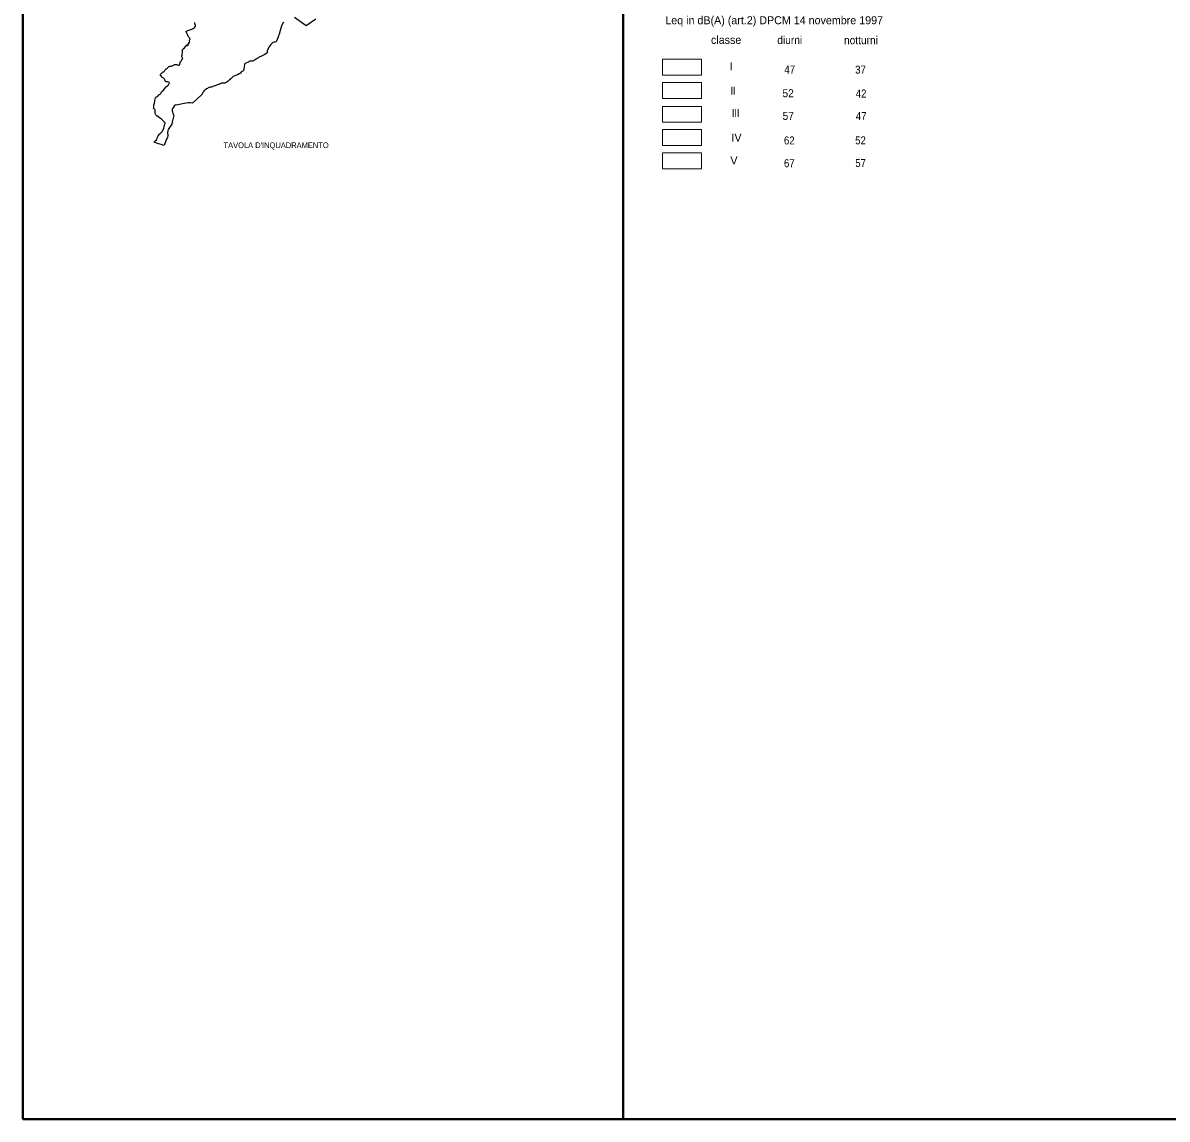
# Model space of a CAD drawing. Extents: x 654952 to 658955, y 890426 to 894481.
# Drawn here: x 654952 to 656954, y 890426 to 892344 of the extents above; entities that cross this region are included whole.
import ezdxf
from ezdxf.enums import TextEntityAlignment as Align

# ---------------------------------------------------------------- set-up
doc = ezdxf.new("R2010")
doc.units = 0
doc.header["$LTSCALE"] = 4
doc.layers.add('60', color=7, linetype='Continuous', lineweight=35)

msp = doc.modelspace()

# ---------------------------------------------------------------- linework, layer by layer
at = {"layer": '60', "lineweight": 40}
for p, q in [((654952.15, 892994.48), (654952.15, 890425.88)), ((656002.15, 892994.48), (656002.15, 890425.88)), ((657055.17, 890425.88), (654952.15, 890425.88))]:
    msp.add_line(p, q, dxfattribs=at)
at = {"layer": '60', "lineweight": 25}
for points in [[(655243.29, 892308.87), (655242.85, 892309.11), (655242.53, 892309.19), (655242.27, 892309.55), (655242.27, 892309.72), (655242.53, 892310.16), (655242.99, 892310.28), (655243.61, 892310.35), (655244.07, 892310.96), (655243.75, 892312.08), (655243.87, 892314.07), (655244.51, 892315), (655244.45, 892316.23), (655243.95, 892317.28), (655242.85, 892318.4), (655241.77, 892319.52), (655241.19, 892320.39), (655240.43, 892321.95), (655240.05, 892323.28), (655239.53, 892324.67), (655239.21, 892325.72), (655238.71, 892326.35), (655237.67, 892327.32), (655237.41, 892328.07), (655237.49, 892329), (655238.19, 892329.48), (655239.33, 892329.92), (655240.69, 892330.36), (655242.33, 892330.83), (655244.31, 892331.39), (655247.63, 892332.63), (655250.25, 892333.99), (655252.05, 892334.99), (655253.19, 892336.08), (655254.21, 892337.83), (655254.21, 892338.32), (655253.91, 892340.19), (655253.13, 892341.6), (655252.81, 892342.72), (655252.75, 892343.52)], [(655252.75, 892343.52), (655252.75, 892344.52)], [(655408.31, 892345), (655405.95, 892341.12), (655405.19, 892339.47), (655403.55, 892334.71), (655401.11, 892326.08), (655400.23, 892323.31), (655399.53, 892321.2), (655398.25, 892317.72), (655396.97, 892314.51), (655395.63, 892311.96), (655394.49, 892310.48), (655393.41, 892309.96), (655391.83, 892309.72), (655389.59, 892309.15), (655388.43, 892308.36), (655385.81, 892305.68), (655382.55, 892300.96), (655379.87, 892295.88)], [(655464.83, 892350.4), (655447.49, 892338.48), (655427.31, 892353.16)], [(655227.11, 892273.48), (655227.37, 892274.67), (655227.93, 892275.91), (655228.95, 892276.84), (655229.73, 892278), (655230.17, 892279.24), (655231.13, 892280.56), (655231.61, 892280.95), (655231.75, 892281.63), (655231.35, 892282.32), (655230.85, 892283.31), (655230.33, 892284.12), (655230.39, 892285.4), (655230.85, 892287.03), (655231.05, 892289.19), (655231.29, 892291.55), (655231.29, 892293.52), (655231.17, 892294.95), (655231.05, 892295.88), (655231.17, 892296.75), (655231.69, 892297.31), (655232.71, 892298.28), (655234.61, 892300.23), (655236.59, 892302.27), (655237.69, 892303.75), (655238.07, 892305.12), (655238.19, 892305.52), (655238.71, 892305.32), (655239.21, 892304.52), (655239.65, 892303.96), (655240.87, 892304.04), (655241.37, 892304.71), (655241.45, 892305.64), (655241.37, 892306.63), (655241.45, 892307.39), (655241.71, 892307.44), (655242.33, 892307.68), (655242.93, 892307.92), (655243.29, 892308.31), (655243.29, 892308.87)], [(655379.87, 892295.88), (655379.55, 892294.11), (655379.61, 892292.63), (655379.19, 892291.6), (655377.71, 892290.19), (655375.41, 892288.59), (655372.09, 892286.91), (655368.45, 892285.19), (655366.23, 892284.15), (655364.37, 892282.47), (655362.09, 892281.4), (655360.41, 892280.48), (655357.41, 892278.32), (655355.37, 892277.52), (655353.53, 892276.91), (655350.85, 892276.52), (655348.93, 892276.52), (655347.65, 892276.15), (655346.55, 892275.04), (655344.91, 892274.48), (655342.17, 892273.48), (655340.95, 892272.8), (655339.93, 892271.27), (655339.59, 892270.08), (655339.23, 892267.88), (655338.41, 892262), (655337.97, 892260.39), (655337.13, 892259.28), (655335.73, 892258.47), (655334.13, 892257.28), (655332.53, 892255.99), (655330.23, 892254.68), (655327.55, 892253.03), (655323.85, 892251.4), (655320.27, 892249.8), (655319.01, 892248.55), (655317.33, 892247.12), (655315.67, 892245.76), (655313.69, 892243.96), (655311.15, 892241.87)], [(655192.71, 892253.15), (655193.33, 892254.12), (655193.91, 892255), (655194.99, 892255.6), (655195.89, 892256.16), (655196.61, 892257.36), (655197.03, 892257.76), (655197.73, 892257.95), (655198.69, 892258.32), (655199.77, 892259.43), (655200.41, 892260.4), (655201.17, 892261.4), (655201.69, 892262.28), (655202.07, 892263.15), (655202.59, 892263.32), (655203.35, 892263.32), (655203.99, 892263.76), (655205.07, 892264.63), (655205.71, 892265.39), (655206.29, 892266), (655206.73, 892266.75), (655207.43, 892267.24), (655208.19, 892267.48), (655209.21, 892267.72), (655210.43, 892267.96), (655211.91, 892268.23), (655213.43, 892268.52), (655214.59, 892269.04), (655215.81, 892269.88), (655216.77, 892270.32), (655217.65, 892270.64), (655219.05, 892270.76), (655220.27, 892270.76), (655221.35, 892270.64), (655222.65, 892270.39), (655223.59, 892269.88), (655225.25, 892269.96), (655226.41, 892270.76), (655226.97, 892272.12), (655227.11, 892273.48)], [(655183.11, 892208.27), (655183.37, 892210.68), (655183.95, 892212.28), (655185.03, 892213.52), (655186.11, 892214.4), (655187.91, 892215.12), (655189.05, 892216.12), (655190.13, 892217.67), (655192.05, 892219.03), (655193.33, 892220.28), (655194.15, 892221.64), (655194.75, 892223.07), (655195.83, 892224.43), (655197.87, 892226.08), (655199.97, 892228.44), (655202.07, 892231.07), (655203.23, 892232.2), (655205.55, 892234.12), (655206.81, 892235.48), (655208.23, 892237.4), (655208.35, 892238.52), (655207.77, 892239.44), (655206.87, 892240.12), (655205.67, 892240.63), (655204.59, 892240.63), (655203.75, 892240.56), (655202.85, 892240.75), (655201.89, 892241.31), (655201.13, 892242.4), (655200.17, 892243.96), (655199.73, 892245.47), (655198.71, 892246.56), (655197.93, 892247.07), (655197.03, 892247.76), (655196.01, 892248.19), (655194.99, 892249.48), (655193.79, 892250.84), (655192.65, 892251.72), (655192.51, 892252.27), (655192.71, 892253.15)], [(655311.15, 892241.87), (655308.93, 892239.96), (655305.61, 892238.28), (655305.03, 892238.35), (655302.61, 892238.28), (655300.83, 892238.16), (655299.29, 892238.35), (655298.59, 892237.84), (655296.75, 892236.8), (655294.89, 892235.88), (655293.81, 892235.76), (655292.71, 892235.51), (655291.05, 892234.83), (655288.75, 892233.4), (655287.53, 892233.4), (655284.53, 892232.28), (655282.23, 892231.55), (655280.37, 892231.4), (655277.89, 892230.55), (655276.39, 892229.88), (655274.93, 892229.07), (655273.53, 892228.64), (655272.81, 892228.2), (655271.91, 892227.35), (655270.39, 892226.08), (655268.41, 892224.6), (655268.41, 892223.68), (655267.53, 892222.36), (655266.17, 892221.52), (655265.67, 892219.16), (655265.47, 892218.28), (655264.65, 892217.8), (655249.07, 892203.51), (655244.55, 892203.95), (655242.31, 892204.07), (655241.03, 892203.88), (655238.55, 892203.4), (655234.27, 892202.59), (655226.09, 892200.92), (655220.41, 892199.8)], [(655189.31, 892132.39), (655184.97, 892134.15), (655181.95, 892135.32), (655182.43, 892136.08), (655186.69, 892139.76), (655186.89, 892142.16), (655187.53, 892144.08), (655189.05, 892146.2), (655191.03, 892148.87), (655192.95, 892151.04), (655194.29, 892152.15), (655195.19, 892152.76), (655196.33, 892154.92), (655198.45, 892159.08), (655199.33, 892162.44), (655199.91, 892164.28), (655200.69, 892166.4), (655201.11, 892167.6), (655200.99, 892168.96), (655199.97, 892170.32), (655197.55, 892172.6), (655193.97, 892175.71), (655190.91, 892177.8), (655186.35, 892181.35), (655184.71, 892183.15), (655183.61, 892185.07), (655183.55, 892188.04), (655183.69, 892191.51), (655183.17, 892192.48), (655181.83, 892193.24), (655180.87, 892194.16), (655181.01, 892196.04), (655181.39, 892198.52), (655181.45, 892200), (655181.31, 892201), (655181.51, 892201.56), (655182.27, 892202.99), (655182.67, 892204.28), (655182.79, 892206.03), (655183.11, 892208.27)], [(655220.41, 892199.8), (655218.05, 892199.63), (655216.89, 892199.24), (655216.53, 892198.2), (655214.91, 892195.35), (655214.09, 892193.68), (655213.19, 892192.36), (655213.25, 892189.76), (655213.77, 892188.23), (655214.61, 892185.6), (655215.49, 892182.92), (655215.93, 892182), (655215.49, 892179.83), (655214.53, 892175.04), (655214.01, 892172.52), (655213.51, 892171.47), (655213.25, 892170.72), (655213.59, 892169.84), (655213.77, 892169.23), (655213.47, 892168.24), (655212.99, 892167.52), (655212.45, 892166.64), (655211.37, 892165), (655209.91, 892162.68), (655208.49, 892160.75), (655207.19, 892158.72), (655206.09, 892157.24), (655205.63, 892154.64), (655205.31, 892152.12), (655205.05, 892150.2), (655205.55, 892148.47), (655205.95, 892147.2), (655205.89, 892146.27), (655205.27, 892144), (655204.67, 892141.91), (655203.61, 892140.11), (655202.93, 892139.23), (655199.23, 892129.2), (655194.19, 892130.76), (655189.31, 892132.39)]]:
    msp.add_lwpolyline(points, dxfattribs=at)
at = {"layer": '60', "lineweight": 13}
for points in [[(656070.74, 892280), (656139.28, 892280), (656139.28, 892252.28), (656070.74, 892252.28)], [(656070.74, 892239.3), (656139.28, 892239.3), (656139.28, 892211.58), (656070.74, 892211.58)], [(656070.74, 892197.72), (656139.28, 892197.72), (656139.28, 892170), (656070.74, 892170)], [(656070.74, 892157), (656139.28, 892157), (656139.28, 892129.28), (656070.74, 892129.28)], [(656070.74, 892116.28), (656139.28, 892116.28), (656139.28, 892088.56), (656070.74, 892088.56)]]:
    msp.add_lwpolyline(points, close=True, dxfattribs=at)

# ---------------------------------------------------------------- texts
at = {"layer": '60'}
msp.add_text('Leq in dB(A) (art.2) DPCM 14 novembre 1997', height=14, dxfattribs=at).set_placement((656075.94, 892341.34))
for s, p in [('classe', (656182.35, 892307.02)), ('I', (656191.37, 892260.49)), ('IV', (656200.45, 892135.93)), ('V', (656195.96, 892095.99))]:
    msp.add_text(s, height=14, dxfattribs=at).set_placement(p, align=Align.CENTER)
for s, width, p in [('diurni', 0.95, (656293.56, 892306.82)), ('notturni', 0.95, (656418.13, 892306.38)), ('47', 0.9, (656293.57, 892255.16)), ('37', 0.9, (656417.41, 892254.98)), ('II', 0.8, (656194.31, 892218.17)), (' 52', 0.95, (656288.36, 892213.62)), ('42', 0.9, (656418.39, 892213.18)), ('III', 0.85, (656198.92, 892178.87)), (' 57', 0.95, (656288.55, 892173.9)), ('47', 0.9, (656418.43, 892173.64)), ('62', 0.9, (656292.81, 892131.1)), ('52', 0.9, (656417.39, 892131.24)), ('67', 0.9, (656292.87, 892091.2)), ('57', 0.9, (656417.57, 892091.62))]:
    msp.add_text(s, height=14, dxfattribs=dict(at, width=width)).set_placement(p, align=Align.CENTER)
at = {"layer": '60', "width": 0.95}
msp.add_text("TAVOLA D'INQUADRAMENTO", height=10, dxfattribs=at).set_placement((655303.13, 892124.64))

doc.saveas('drawing.dxf')
